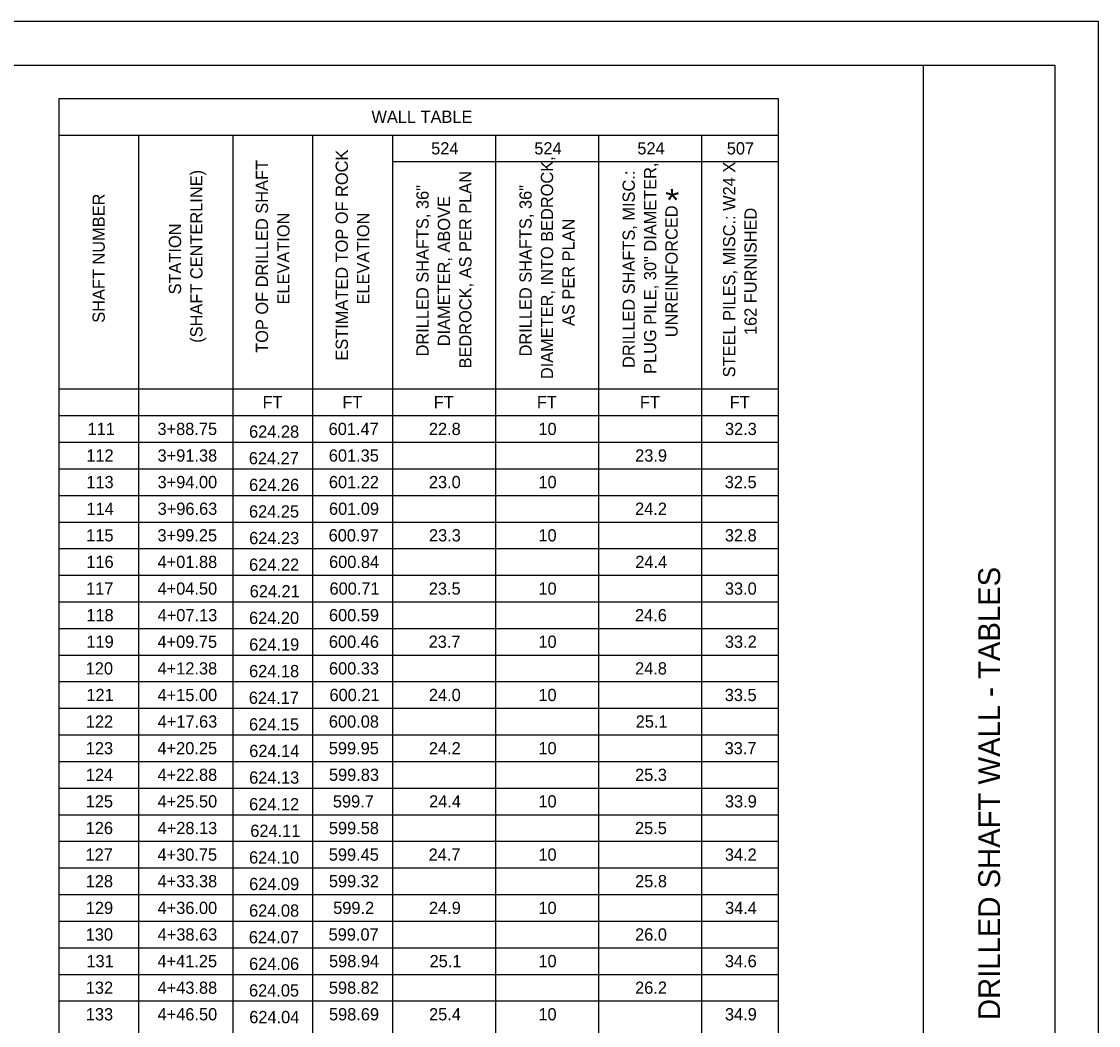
# Model space of a CAD drawing. Extents: x 0 to 34, y 0 to 22.
# Drawn here: x 21.68 to 34, y 10.52 to 22 of the extents above; entities that cross this region are included whole.
import ezdxf

# ---------------------------------------------------------------- set-up
doc = ezdxf.new("R2010")
doc.units = 0
for name, color, linetype in [('BR_P_Gen_Text', 7, 'Continuous'), ('SH_Border', 7, 'Continuous'), ('SH_Cut_Line', 7, 'Continuous'), ('SH_Data', 7, 'Continuous')]:
    doc.layers.add(name, color=color, linetype=linetype)

msp = doc.modelspace()

# ---------------------------------------------------------------- linework, layer by layer
at = {"layer": 'BR_P_Gen_Text'}
for p, q in [((22.105, 21.12), (30.335, 21.12)), ((22.105, 21.12), (22.105, 4.407)), ((30.335, 21.12), (30.335, 4.407)), ((22.105, 20.702), (30.335, 20.702)), ((23.018, 20.702), (23.018, 4.407)), ((24.096, 20.702), (24.096, 4.407)), ((25.009, 20.702), (25.009, 4.407)), ((25.922, 20.702), (25.922, 4.407)), ((27.102, 20.702), (27.102, 4.407)), ((28.281, 20.702), (28.281, 4.407)), ((29.46, 20.702), (29.46, 4.407)), ((25.922, 20.398), (30.335, 20.398)), ((22.105, 17.798), (30.335, 17.798)), ((22.105, 17.494), (30.335, 17.494)), ((22.105, 17.189), (30.335, 17.189)), ((22.105, 16.885), (30.335, 16.885)), ((22.105, 16.581), (30.335, 16.581)), ((22.105, 16.276), (30.335, 16.276)), ((22.105, 15.972), (30.335, 15.972)), ((22.105, 15.668), (30.335, 15.668)), ((22.105, 15.363), (30.335, 15.363)), ((22.105, 15.059), (30.335, 15.059)), ((22.105, 14.754), (30.335, 14.754)), ((22.105, 14.45), (30.335, 14.45)), ((22.105, 14.146), (30.335, 14.146)), ((22.105, 13.841), (30.335, 13.841)), ((22.105, 13.537), (30.335, 13.537)), ((22.105, 13.233), (30.335, 13.233)), ((22.105, 12.928), (30.335, 12.928)), ((22.105, 12.624), (30.335, 12.624)), ((22.105, 12.32), (30.335, 12.32)), ((22.105, 12.015), (30.335, 12.015)), ((22.105, 11.711), (30.335, 11.711)), ((22.105, 11.407), (30.335, 11.407)), ((22.105, 11.102), (30.335, 11.102)), ((22.105, 10.798), (30.335, 10.798))]:
    msp.add_line(p, q, dxfattribs=at)
at = {"layer": 'SH_Border'}
msp.add_line((32, 0.5), (32, 21.5), dxfattribs=at)
msp.add_lwpolyline([(1.5, 21.5), (33.5, 21.5), (33.5, 0.5), (1.5, 0.5)], close=True, dxfattribs=at)
at = {"layer": 'SH_Cut_Line'}
msp.add_lwpolyline([(0, 0), (34, 0), (34, 22), (0, 22)], close=True, dxfattribs=at)

# ---------------------------------------------------------------- texts
at = {"layer": 'BR_P_Gen_Text'}
for s, p in [('WALL TABLE', (25.683, 20.841)), ('524', (26.366, 20.48)), ('524', (27.546, 20.48)), ('524', (28.725, 20.48)), ('507', (29.748, 20.48)), ('FT', (24.437, 17.576)), ('FT', (25.35, 17.576)), ('FT', (26.396, 17.576)), ('FT', (27.575, 17.576)), ('FT', (28.754, 17.576)), ('FT', (29.782, 17.576)), ('111', (22.435, 17.271)), ('3+88.75', (23.235, 17.271)), ('624.28', (24.283, 17.24)), ('601.47', (25.193, 17.271)), ('22.8', (26.34, 17.271)), ('10', (27.593, 17.271)), ('32.3', (29.727, 17.271)), ('112', (22.421, 16.967)), ('3+91.38', (23.236, 16.967)), ('624.27', (24.28, 16.936)), ('601.35', (25.195, 16.967)), ('23.9', (28.7, 16.967)), ('113', (22.421, 16.663)), ('3+94.00', (23.236, 16.663)), ('624.26', (24.283, 16.631)), ('601.22', (25.196, 16.663)), ('23.0', (26.34, 16.663)), ('10', (27.593, 16.663)), ('32.5', (29.725, 16.663)), ('114', (22.423, 16.358)), ('3+96.63', (23.237, 16.358)), ('624.25', (24.282, 16.327)), ('601.09', (25.197, 16.358)), ('24.2', (28.699, 16.358)), ('115', (22.42, 16.054)), ('3+99.25', (23.235, 16.054)), ('624.23', (24.284, 16.023)), ('600.97', (25.193, 16.054)), ('23.3', (26.341, 16.054)), ('10', (27.593, 16.054)), ('32.8', (29.726, 16.054)), ('116', (22.421, 15.75)), ('4+01.88', (23.236, 15.75)), ('624.22', (24.283, 15.718)), ('600.84', (25.198, 15.75)), ('24.4', (28.701, 15.75)), ('117', (22.418, 15.445)), ('4+04.50', (23.236, 15.445)), ('624.21', (24.29, 15.414)), ('600.71', (25.203, 15.445)), ('23.5', (26.339, 15.445)), ('10', (27.593, 15.445)), ('33.0', (29.726, 15.445)), ('118', (22.421, 15.141)), ('4+07.13', (23.237, 15.141)), ('600.59', (25.197, 15.141)), ('24.6', (28.698, 15.141)), ('624.20', (24.283, 15.11)), ('119', (22.422, 14.837)), ('4+09.75', (23.235, 14.837)), ('624.19', (24.284, 14.805)), ('600.46', (25.196, 14.837)), ('23.7', (26.337, 14.837)), ('10', (27.593, 14.837)), ('33.2', (29.726, 14.837)), ('120', (22.414, 14.532)), ('4+12.38', (23.236, 14.532)), ('600.33', (25.197, 14.532)), ('24.8', (28.699, 14.532)), ('624.18', (24.283, 14.501)), ('121', (22.422, 14.228)), ('4+15.00', (23.236, 14.228)), ('624.17', (24.28, 14.196)), ('600.21', (25.203, 14.228)), ('24.0', (26.34, 14.228)), ('10', (27.593, 14.228)), ('33.5', (29.725, 14.228)), ('122', (22.415, 13.924)), ('4+17.63', (23.237, 13.924)), ('600.08', (25.196, 13.924)), ('25.1', (28.706, 13.924)), ('624.15', (24.282, 13.892)), ('123', (22.415, 13.619)), ('4+20.25', (23.235, 13.619)), ('624.14', (24.285, 13.588)), ('599.95', (25.195, 13.619)), ('24.2', (26.34, 13.619)), ('10', (27.593, 13.619)), ('33.7', (29.723, 13.619)), ('124', (22.416, 13.315)), ('4+22.88', (23.236, 13.315)), ('599.83', (25.197, 13.315)), ('25.3', (28.699, 13.315)), ('624.13', (24.284, 13.283)), ('125', (22.414, 13.011)), ('4+25.50', (23.236, 13.011)), ('624.12', (24.283, 12.979)), ('599.7', (25.242, 13.011)), ('24.4', (26.342, 13.011)), ('10', (27.593, 13.011)), ('33.9', (29.727, 13.011)), ('126', (22.414, 12.706)), ('4+28.13', (23.237, 12.706)), ('624.11', (24.297, 12.675)), ('599.58', (25.196, 12.706)), ('25.5', (28.698, 12.706)), ('127', (22.412, 12.402)), ('4+30.75', (23.235, 12.402)), ('624.10', (24.283, 12.37)), ('599.45', (25.195, 12.402)), ('24.7', (26.337, 12.402)), ('10', (27.593, 12.402)), ('34.2', (29.726, 12.402)), ('128', (22.414, 12.098)), ('4+33.38', (23.236, 12.098)), ('624.09', (24.284, 12.066)), ('599.32', (25.196, 12.098)), ('25.8', (28.699, 12.098)), ('129', (22.415, 11.793)), ('4+36.00', (23.236, 11.793)), ('624.08', (24.283, 11.762)), ('599.2', (25.245, 11.793)), ('24.9', (26.341, 11.793)), ('10', (27.593, 11.793)), ('34.4', (29.728, 11.793)), ('130', (22.414, 11.489)), ('4+38.63', (23.237, 11.489)), ('624.07', (24.28, 11.457)), ('599.07', (25.193, 11.489)), ('26.0', (28.699, 11.489)), ('131', (22.422, 11.184)), ('4+41.25', (23.235, 11.184)), ('624.06', (24.283, 11.153)), ('598.94', (25.198, 11.184)), ('25.1', (26.348, 11.184)), ('10', (27.593, 11.184)), ('34.6', (29.726, 11.184)), ('132', (22.415, 10.88)), ('4+43.88', (23.236, 10.88)), ('624.05', (24.282, 10.849)), ('598.82', (25.196, 10.88)), ('26.2', (28.699, 10.88)), ('133', (22.415, 10.576)), ('4+46.50', (23.236, 10.576)), ('624.04', (24.285, 10.544)), ('598.69', (25.197, 10.576)), ('25.4', (26.342, 10.576)), ('10', (27.593, 10.576)), ('34.9', (29.727, 10.576))]:
    msp.add_text(s, height=0.14, dxfattribs=at).set_placement(p)
for s, height, rotation, p in [('ESTIMATED TOP OF ROCK ', 0.14, 90, (25.413, 18.122)), ('TOP OF DRILLED SHAFT ', 0.14, 90, (24.5, 18.211)), ('DIAMETER, INTO BEDROCK, ', 0.14, 90, (27.761, 17.91)), ('PLUG PILE, 30" DIAMETER, ', 0.14, 90, (28.941, 17.97)), ('STEEL PILES, MISC.: W24 X ', 0.14, 90, (29.845, 17.931)), ('(SHAFT CENTERLINE)', 0.14, 90, (23.75, 18.326)), ('BEDROCK, AS PER PLAN', 0.14, 90, (26.827, 18.033)), ('DRILLED SHAFTS, MISC.: ', 0.14, 90, (28.696, 18.038)), ('DRILLED SHAFTS, 36" ', 0.14, 90, (26.337, 18.17)), ('DRILLED SHAFTS, 36" ', 0.14, 90, (27.516, 18.17)), ('*', 0.28, 73.734, (29.302, 19.89)), ('SHAFT NUMBER', 0.14, 90, (22.632, 18.555)), ('DIAMETER, ABOVE ', 0.14, 90, (26.582, 18.287)), ('UNREINFORCED', 0.14, 90, (29.186, 18.389)), ('162 FURNISHED', 0.14, 90, (30.09, 18.414)), ('ELEVATION', 0.14, 90, (24.745, 18.764)), ('ELEVATION', 0.14, 90, (25.658, 18.764)), ('AS PER PLAN', 0.14, 90, (28.006, 18.518)), ('STATION                                                           ', 0.14, 90, (23.505, 18.879))]:
    msp.add_text(s, height=height, rotation=rotation, dxfattribs=at).set_placement(p)
at = {"layer": 'SH_Data'}
msp.add_text('DRILLED SHAFT WALL - TABLES', height=0.25, rotation=90, dxfattribs=at).set_placement((32.875, 10.58))

doc.saveas('drawing.dxf')
